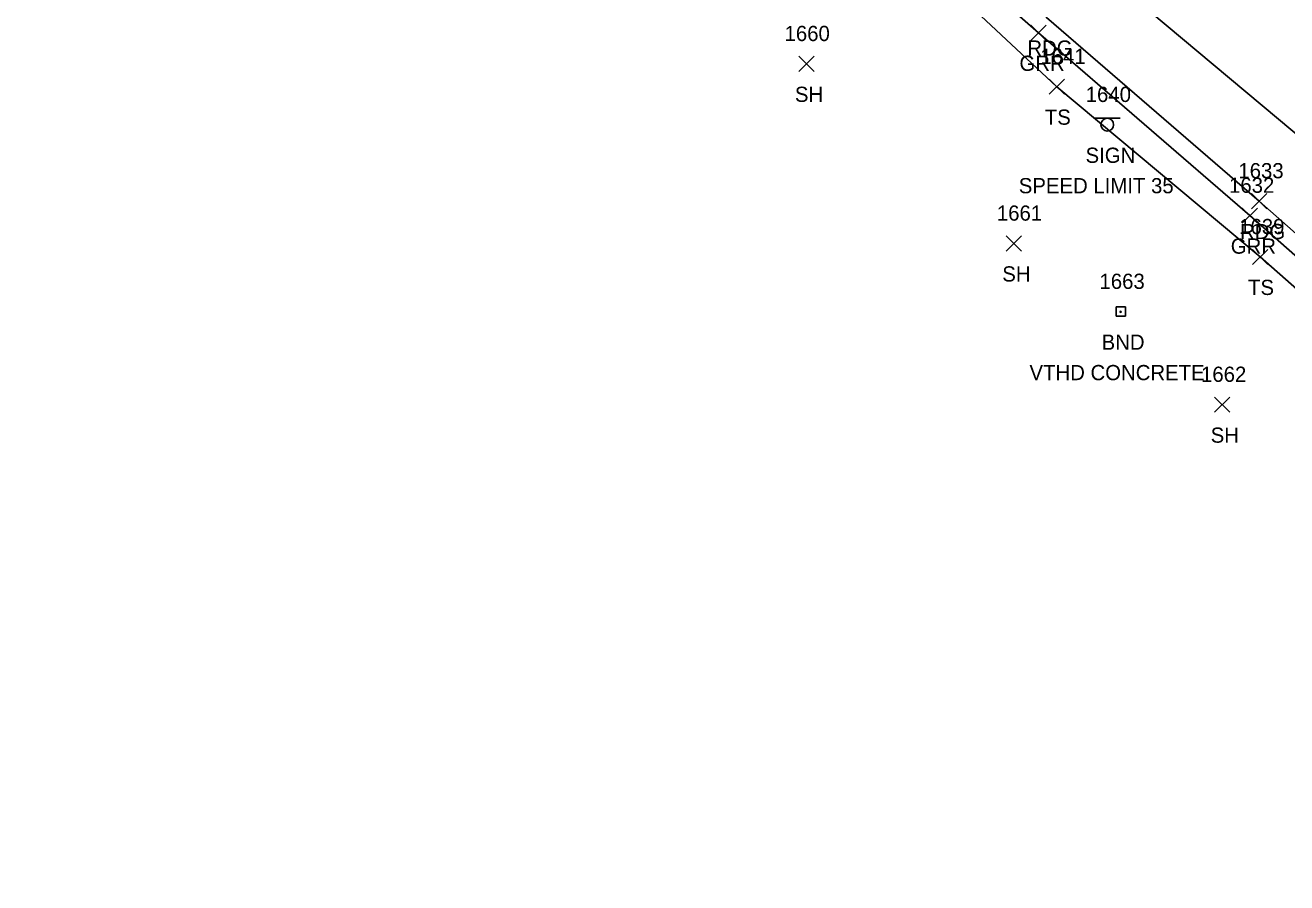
# Model space of a CAD drawing. Extents: x 1629176 to 1637209, y 606063 to 610167.
# Drawn here: x 1629782.2 to 1629948.1, y 606615.6 to 606728.3 of the extents above; entities that cross this region are included whole.
import ezdxf

# ---------------------------------------------------------------- set-up
doc = ezdxf.new("R2010")
doc.units = 0
for name, color, linetype in [('L_A', 7, 'Continuous'), ('L_I', 7, 'Continuous'), ('L_TIC', 7, 'Continuous'), ('LELB', 7, 'Continuous'), ('M_A', 7, 'Continuous'), ('M_C', 7, 'Continuous'), ('M_I', 7, 'Continuous'), ('MHBP', 7, 'Continuous'), ('P_A', 7, 'Continuous'), ('P_I', 7, 'Continuous'), ('P_TIC', 7, 'Continuous'), ('PEU', 7, 'Continuous'), ('PRC', 7, 'Continuous'), ('R_A', 7, 'Continuous'), ('R_I', 7, 'Continuous'), ('R_TIC', 7, 'Continuous'), ('RGR', 7, 'Continuous'), ('S_A', 7, 'Continuous'), ('S_C', 7, 'Continuous'), ('S_I', 7, 'Continuous'), ('SSGN', 7, 'Continuous')]:
    doc.layers.add(name, color=color, linetype=linetype)

msp = doc.modelspace()

# ---------------------------------------------------------------- linework, layer by layer
at = {"layer": 'L_TIC'}
for points in [[(1629883.92, 606722.26), (1629885.92, 606724.26)], [(1629885.92, 606722.26), (1629883.92, 606724.26)], [(1629916.84, 606719.26), (1629918.84, 606721.26)], [(1629918.84, 606719.26), (1629916.84, 606721.26)], [(1629911.17, 606698.65), (1629913.17, 606700.65)], [(1629913.17, 606698.65), (1629911.17, 606700.65)], [(1629943.56, 606696.88), (1629945.56, 606698.88)], [(1629945.56, 606696.88), (1629943.56, 606698.88)], [(1629938.58, 606677.46), (1629940.58, 606679.46)], [(1629940.58, 606677.46), (1629938.58, 606679.46)]]:
    msp.add_lwpolyline(points, dxfattribs=at)
at = {"layer": 'LELB'}
msp.add_lwpolyline([(1629974.23, 606671.73), (1629944.56, 606697.88), (1629917.84, 606720.26), (1629895.86, 606740.8), (1629872.45, 606761.2), (1629853.73, 606776.41), (1629836.55, 606788.97), (1629824.22, 606793.63), (1629808.76, 606792.78), (1629777.19, 606783.69), (1629732.57, 606770.35)], dxfattribs=at)
at = {"layer": 'MHBP'}
for p, q in [((1629926.88, 606691.33), (1629925.63, 606691.33)), ((1629925.63, 606691.33), (1629925.63, 606690.08)), ((1629926.88, 606691.33), (1629925.63, 606691.33)), ((1629925.63, 606691.33), (1629925.63, 606690.08)), ((1629926.88, 606690.08), (1629926.88, 606691.33)), ((1629926.88, 606690.08), (1629926.88, 606691.33)), ((1629925.63, 606690.08), (1629926.88, 606690.08)), ((1629925.63, 606690.08), (1629926.88, 606690.08))]:
    msp.add_line(p, q, dxfattribs=at)
msp.add_circle((1629926.23, 606690.67), 0.0833, dxfattribs=at)
at = {"layer": 'P_TIC'}
for points in [[(1629943.44, 606704.22), (1629945.44, 606706.22)], [(1629945.44, 606704.22), (1629943.44, 606706.22)]]:
    msp.add_lwpolyline(points, dxfattribs=at)
at = {"layer": 'PEU'}
msp.add_lwpolyline([(1629882.91, 606759.19), (1629916.47, 606729.34), (1629944.44, 606705.22), (1629977.31, 606676.19)], dxfattribs=at)
at = {"layer": 'PRC'}
msp.add_lwpolyline([(1629847.76, 606817.22), (1629856.43, 606802.15), (1629871.31, 606783.29), (1629889.77, 606765.03), (1629921.75, 606737.15), (1629950.99, 606712.6), (1629983.98, 606682.75), (1630026.35, 606648.49), (1630062.55, 606615.61)], dxfattribs=at)
at = {"layer": 'R_TIC'}
for points in [[(1629914.43, 606726.34), (1629916.43, 606728.34)], [(1629916.43, 606726.34), (1629914.43, 606728.34)], [(1629942.21, 606702.31), (1629944.21, 606704.31)], [(1629944.21, 606702.31), (1629942.21, 606704.31)]]:
    msp.add_lwpolyline(points, dxfattribs=at)
at = {"layer": 'RGR'}
msp.add_lwpolyline([(1629610.69, 606767.66), (1629614.78, 606771.08), (1629618.2, 606772.52), (1629623.02, 606773.09), (1629651.93, 606771.73), (1629678.65, 606772.42), (1629701.28, 606773.86), (1629724.79, 606776.82), (1629746.85, 606781.44), (1629773.74, 606788.69), (1629807.56, 606798.03), (1629819.63, 606798.3), (1629831.2, 606794.55), (1629845.84, 606786.32), (1629881.37, 606757.13), (1629915.43, 606727.34), (1629943.21, 606703.31), (1629976.52, 606673.99)], dxfattribs=at)
at = {"layer": 'SSGN'}
for p, q in [((1629922.83, 606716.11), (1629926.16, 606716.11)), ((1629924.47, 606715.27), (1629924.47, 606715.27))]:
    msp.add_line(p, q, dxfattribs=at)
msp.add_circle((1629924.47, 606715.27), 0.833, dxfattribs=at)

# ---------------------------------------------------------------- texts
at = {"layer": 'L_A'}
for s, p in [('SH', (1629883.4, 606718.26)), ('TS', (1629916.25, 606715.26)), ('SH', (1629910.66, 606694.65)), ('TS', (1629942.97, 606692.88)), ('SH', (1629938.06, 606673.46))]:
    msp.add_text(s, height=2, dxfattribs=at).set_placement(p)
at = {"layer": 'L_I'}
for s, p in [('1660', (1629882.04, 606726.26)), ('1641', (1629915.67, 606723.26)), ('1661', (1629909.95, 606702.65)), ('1639', (1629941.81, 606700.88)), ('1662', (1629936.79, 606681.46))]:
    msp.add_text(s, height=2, dxfattribs=at).set_placement(p)
at = {"layer": 'M_A'}
msp.add_text('BND', height=2, dxfattribs=at).set_placement((1629923.72, 606685.68))
at = {"layer": 'M_C'}
msp.add_text('VTHD CONCRETE', height=2, dxfattribs=at).set_placement((1629914.24, 606681.68))
at = {"layer": 'M_I'}
msp.add_text('1663', height=2, dxfattribs=at).set_placement((1629923.44, 606693.68))
at = {"layer": 'P_A'}
for p in [(1629913.96, 606724.34), (1629941.93, 606700.22)]:
    msp.add_text('RDG', height=2, dxfattribs=at).set_placement(p)
at = {"layer": 'P_I'}
msp.add_text('1633', height=2, dxfattribs=at).set_placement((1629941.7, 606708.22))
at = {"layer": 'R_A'}
for p in [(1629912.92, 606722.34), (1629940.7, 606698.31)]:
    msp.add_text('GRR', height=2, dxfattribs=at).set_placement(p)
at = {"layer": 'R_I'}
msp.add_text('1632', height=2, dxfattribs=at).set_placement((1629940.47, 606706.31))
at = {"layer": 'S_A'}
msp.add_text('SIGN', height=2, dxfattribs=at).set_placement((1629921.61, 606710.25))
at = {"layer": 'S_C'}
msp.add_text('SPEED LIMIT 35', height=2, dxfattribs=at).set_placement((1629912.83, 606706.25))
at = {"layer": 'S_I'}
msp.add_text('1640', height=2, dxfattribs=at).set_placement((1629921.63, 606718.25))

doc.saveas('drawing.dxf')
